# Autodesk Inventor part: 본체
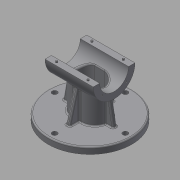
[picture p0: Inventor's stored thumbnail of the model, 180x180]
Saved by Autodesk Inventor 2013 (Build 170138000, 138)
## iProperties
Created: 2015-12
Part Number: 본체
Material: 알루미늄 6061
Document SubType Name: Modeling
Designer: mduedu
Density: 2.71 g/cm^3
Author: mduedu
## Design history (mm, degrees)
sketch "스케치1"
  geometry: C1 r 65 at (0, 0); 1 further point
  constraints: 1 centre point, 1 coincident
  dimensions: "d124" = 130 diameter of C1
extrude "돌출1" new body sketch "스케치1" distance "d3" = 10; taper "d4" = 0 deg
sketch "스케치2"
  geometry: C1 r 32.5 at (80, 0); 1 further point
  constraints: 1 centre point, 1 horizontal alignment
  dimensions: "d5" = 65 diameter of C1; "d125" = 80 distance of C1.centre point (0, 0)
extrude "돌출2" join sketch "스케치2" stored distance "d7" = 75; taper "d8" = 0 deg
sketch "스케치3"
  geometry: L1 (-27.5, -20)-(27.5, -20); L2 (27.5, -20)-(27.5, 20); L3 (27.5, 20)-(-27.5, 20); L4 (-27.5, 20)-(-27.5, -20); L5 (-27.5, -20)-(27.5, 20); L6 (27.5, -20)-(-27.5, 20); 1 further point
  constraints: 12 end point, 2 midpoint, 2 parallel, 1 horizontal, 1 perpendicular
  dimensions: "d9" = 55 distance of L2.end L3.end; "d11" = 40 distance of L1.end L2.end
extrude "돌출3" new body sketch "스케치3" stored distance "d12" = 75; taper "d13" = 0 deg
fillet "모깎기1"
fillet "모깎기2"
feature "결합1"
  node "솔리드2"
sketch "스케치4"
  geometry: L1 (-37.5, 47.5)-(37.5, 47.5) reference; L2 (32.5, 47.5)-(39.112, 10); L3 (37.5, 47.5)-(37.5, 112.5) reference; L4 (65, 10)-(-65, 10) reference; 1 further point
  constraints: 2 end point, 2 point on line
  dimensions: "d15" = 5 distance from line of L2.start L3; "d126" = 80 deg angle of L2 L1
sketch "스케치5"
  geometry: L1 (10, 35)-(56.569, 22.522); L2 (10, -65)-(10, 65) reference; L3 (10, 20)-(54.383, 20) reference; A1 r 32.5 centre (80, 0) between (56.569, 22.522) and (54.383, 20) reference; 1 further point
  constraints: 2 end point, 1 point on circle, 1 point on line
  dimensions: "d127" = 75 deg angle of L1 L2; "d128" = 15 distance of L1.start L3.start
feature "리브1" dims "d19" = 1, "d20" = 6, "d21" = 0, "d22" = 0, "d23" = 1, "d24" = 1
feature "리브2" dims "d25" = 1, "d26" = 6, "d27" = 0, "d28" = 0, "d29" = 1, "d30" = 1
fillet "모깎기4" dims "d31" = 2
fillet "모깎기5" dims "d32" = 2
fillet "모깎기6" dims "d33" = 2
fillet "모깎기7" dims "d41" = 2
hole "구멍2" diameter "d44" = 45; stored, may be unused: countersink angle "d48" = 90 deg, drill point angle "d50" = 118 deg; dims "d42" = 10, "d43" = 10, "d45" = 6, "d46" = 4, "d47" = 2, "d49" = 8
sketch "스케치7" dims "d52" = 26.5
  geometry: L1 (0, 0)-(32.5, 0); L2 (0, 0)-(22.981, 22.981); A1 r 32.5 centre (0, 0) between (32.5, 0) and (22.981, 22.981) reference; 3 further points
  constraints: 4 end point, 2 point on circle, 1 coincident, 1 horizontal, 1 point on line, 3 other
  dimensions: "d51" = 45 deg angle of L2 L1
hole "구멍3" sketch "스케치7" at (18.738, 18.738) diameter "d54" = 2.459; stored, may be unused: countersink angle "d58" = 90 deg, drill point angle "d60" = 118 deg; dims "d55" = 8, "d56" = 4, "d57" = 2, "d59" = 10
sketch "스케치9"
  geometry: L1 (-75, 82.5)-(75, 82.5); L2 (75, 82.5)-(75, 0); L3 (75, 0)-(-75, 0); L4 (-75, 0)-(-75, 82.5); C1 r 32.5 at (0, 0) reference; 2 further points
  constraints: 8 end point, 2 parallel, 1 coincident, 1 horizontal, 1 midpoint, 1 perpendicular
  dimensions: "d71" = 50 distance edge to line of C1 L1; "d116" = 150 distance between parallel lines of L2 L4
extrude "돌출5" cut sketch "스케치9" stored distance "d73" = 0; taper "d74" = 0 deg
node "작업 평면1"
sketch "스케치10"
  geometry: L1 (-7.5, 15)-(7.5, 15); L2 (-7.5, -15)-(7.5, -15); A1 r 20 centre (-7.5, 0) between (-7.5, 20) and (-26.977, 4.545) reference; A2 r 20 centre (7.5, 0) between (26.977, 4.545) and (7.5, 20) reference; A3 r 15 centre (-7.5, 0) between (-7.5, 15) and (-7.5, -15); A4 r 15 centre (7.5, 0) between (7.5, -15) and (7.5, 15); 1 further point
  constraints: 7 point on circle, 4 end point, 4 tangent, 3 point on line, 2 centre point, 2 coincident, 1 horizontal
  dimensions: "d77" = 5 radial gap between concentric circles of A3 A1
extrude "돌출6" cut sketch "스케치10" stored distance "d78" = 50; taper "d79" = 0 deg
fillet "모깎기10" dims "d80" = 3
sketch "스케치11"
  geometry: 2 further points
  constraints: 1 coincident
hole "구멍4" sketch "스케치11" at (0, 0) diameter "d81" = 12; stored, may be unused: countersink angle "d85" = 90 deg, drill point angle "d87" = 118 deg; dims "d82" = 8, "d83" = 40, "d84" = 10, "d86" = 10
sketch "스케치12"
  geometry: C1 r 10 at (0, 0); 1 further point
  constraints: 1 centre point, 1 coincident
  dimensions: "d88" = 20 diameter of C1
extrude "돌출7" cut sketch "스케치12" distance "d89" = 5; taper "d90" = 0 deg
chamfer "모따기1" distance "d91" = 1; stored, may be unused: second distance "d92" = 2, angle "d93" = 45 deg
fillet "모깎기11" dims "d94" = 0.5
fillet "모깎기12" dims "d115" = 0.3
sketch "스케치15"
  geometry: L1 (-75, 55)-(-75, 65) reference; L2 (0, 65)-(0, 55) reference; L3 (-75, 60)-(0, 60); C1 r 1.5 at (-62, 60); 1 further point
  constraints: 2 end point, 2 midpoint, 1 centre point, 1 point on line
  dimensions: "d117" = 3 diameter of C1; "d118" = 13 distance from line of C1.centre L1
extrude "돌출8" join sketch "스케치15" distance "d119" = 1.8; taper "d120" = 0 deg
chamfer "모따기2" distance "d121" = 0.5; stored, may be unused: second distance "d122" = 2, angle "d123" = 45 deg
sketch "스케치18" dims "d141" = 110
  geometry: C1 r 63 at (0, 0) reference; 2 further points
  constraints: 2 vertical alignment, 1 coincident, 2 other
hole "구멍8" sketch "스케치18" at (0, 55) diameter "d142" = 8; stored, may be unused: countersink angle "d146" = 90 deg, drill point angle "d148" = 118 deg; dims "d143" = 6, "d144" = 4, "d145" = 2, "d147" = 8
node "솔리드1"
mirror "대칭1"
mirror "대칭2"
pattern_circular "원형 패턴1" dims angle "d62" = 360 deg
mirror "대칭3"
mirror "대칭5"
mirror "대칭6"
pattern_circular "원형 패턴2" dims angle "d150" = 360 deg
mirror "대칭7"
